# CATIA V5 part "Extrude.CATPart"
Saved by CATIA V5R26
Part number: Extrude
Bounding box of the stored display mesh (mm): x -267.322 to 261.043, y 0 to 333.526, z 0 to 300.249
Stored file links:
  D:\LinkedIn Learning\NURBS\CATIA\Class Parts\Extrude.CATPart
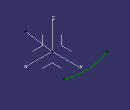
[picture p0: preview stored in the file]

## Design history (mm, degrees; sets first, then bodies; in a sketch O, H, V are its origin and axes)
AxisSystem1: origin (0, 0, 0), X (1, 0, 0), Y (0, 1, 0), Z (0, 0, 1)
Set1
  St3DCurveFeature1 "CATSt3DCurveFeatureName": Order 6, CreationType 1, ClosureMode false, ConstructionPoints ({point type Coord, X -267.3218, Y 276.8681, Z 0}; {point type Coord, X -12.3983, Y 377.3344, Z 0}; {point type Coord, X 176.2624, Y 299.6682, Z 0}), SymmetryMode false
  Line1: stored without definition
Body1 (main body)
